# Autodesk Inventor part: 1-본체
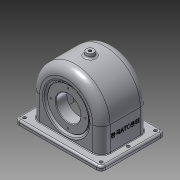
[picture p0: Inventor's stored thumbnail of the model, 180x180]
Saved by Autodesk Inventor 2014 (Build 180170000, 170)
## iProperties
Created: 2015-09
Part Number: 1-본체
Material: 알루미늄 6061
Document SubType Name: Modeling
Designer: Administrator
Density: 2.71 g/cm^3
Appearance: 알루미늄 - 평지
Mass: 735.164 g
Surface Area: 899.785 cm^2
Volume: 271.278 cm^3
Author: Administrator
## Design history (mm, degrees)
sketch "스케치2"
  geometry: L1 (57, 40)-(57, -7); L2 (-57, 40)-(-57, -7); L3 (57, -7)-(-57, -7); C1 r 51 at (0, 40); A1 r 57 centre (0, 40) between (57, 40) and (-57, 40); 2 further points
  constraints: 6 end point, 2 centre point, 2 point on circle, 2 tangent, 1 perpendicular, 1 vertical alignment
  dimensions: "d4" = 51 radius of C1; "d6" = 6 radial gap between concentric circles of C1 A1; "d27" = 40 distance of point (0, 0) C1.centre
extrude "돌출2" join sketch "스케치2" stored distance "d7" = 77; taper "d8" = 0 deg
fillet "모깎기1" dims "d11" = 14
feature "쉘4" dims "d30" = 6, "d31" = 5
sketch "스케치12"
  geometry: L1 (-43, -38.5)-(43, -38.5) reference; L2 (-57, -24.5)-(-57, 24.5) reference; L3 (43, 38.5)-(-43, 38.5) reference; L4 (57, -24.5)-(57, 24.5) reference; L5 (-70, -52)-(70, -52); L6 (70, -52)-(70, 52); L7 (70, 52)-(-70, 52); L8 (-70, 52)-(-70, -52); A1 r 14 centre (-43, -24.5) between (-57, -24.5) and (-43, -38.5) reference; A2 r 14 centre (-43, 24.5) between (-43, 38.5) and (-57, 24.5) reference; A3 r 14 centre (43, 24.5) between (57, 24.5) and (43, 38.5) reference; A4 r 14 centre (43, -24.5) between (43, -38.5) and (57, -24.5) reference; 3 further points
  constraints: 8 end point, 2 midpoint, 2 parallel, 1 horizontal, 1 horizontal alignment, 1 perpendicular, 1 vertical alignment
  dimensions: "d32" = 104 distance of L7.end L5.start; "d33" = 140 distance of L6.end L7.end
extrude "돌출5" join sketch "스케치12" distance "d34" = 7; taper "d35" = 0 deg
sketch "스케치8"
  geometry: L1 (-33.5, 40)-(-17.5, 40); L2 (-17.5, 40)-(-17.5, 68); L3 (-17.5, 68)-(-33.5, 81.426); L4 (-33.5, 81.426)-(-33.5, 40); L5 (-52, -7)-(52, -7) reference; L6 (-33.5, 40)-(-33.5, 83) reference; 1 further point
  constraints: 8 end point, 1 collinear, 1 horizontal, 1 parallel, 1 perpendicular
  dimensions: "d16" = 50 deg angle of L2 L3; "d17" = 16 distance of L1.start L1.end; "d18" = 28 distance of L1.end L2.end; "d36" = 47 distance from line of L1.start L5
revolve "회전1" sketch "스케치8" stored, may be unused: angle "d19" = 90 deg
sketch "스케치9"
  geometry: C1 r 31 at (0, -40); A1 r 43 centre (0, -40) between (-43, -40) and (43, -40) reference; 1 further point
  constraints: 1 centre point, 1 coincident
  dimensions: "d20" = 62 diameter of C1
extrude "돌출3" join sketch "스케치9" distance "d21" = 10; taper "d22" = 0 deg
node "작업 평면1"
sketch "스케치10"
  geometry: C1 r 6 at (70, 52); 1 further point
  constraints: 1 centre point, 1 coincident
  dimensions: "d24" = 12 diameter of C1
extrude "돌출4" join sketch "스케치10" stored distance "d25" = 10; taper "d26" = 10 deg
sketch "스케치16"
  geometry: L1 (-38.5, 40)-(-38.5, 77.195); L2 (-38.5, 77.195)-(-33.5, 73); L3 (-33.5, 73)-(-33.5, 40); L4 (-33.5, 40)-(-38.5, 40); L5 (-24.5, 40)-(24.5, 40) reference; L6 (-33.5, 81.426)-(-33.5, -1.426) reference; L7 (-38.5, 40)-(-38.5, 83) reference; L8 (-24.5, 40)-(-33.5, 40) reference; 1 further point
  constraints: 8 end point, 2 point on line, 1 collinear, 1 parallel, 1 perpendicular, 1 vertical
  dimensions: "d45" = 50 deg angle of L6 L2; "d46" = 33 distance from line of L8 L2.end
revolve "회전2" sketch "스케치16" stored, may be unused: angle "d47" = 90 deg
sketch "스케치17"
  geometry: C1 r 33 at (0, 0) reference; C2 r 33 at (0, 0); 1 further point
  constraints: 1 centre point, 1 coincident
  dimensions: "d48" = 66 diameter of C2
extrude "돌출8" join sketch "스케치17" distance "d49" = 2; taper "d50" = 0 deg
hole "구멍1" diameter "d53" = 40; stored, may be unused: countersink angle "d57" = 90 deg, drill point angle "d59" = 118 deg; dims "d51" = 10, "d52" = 10, "d54" = 6, "d55" = 4, "d56" = 2, "d58" = 8
sketch "스케치18"
  geometry: L1 (0, 0)-(0, 28); C1 r 20 at (0, 0) reference; 1 further point
  constraints: 2 end point, 1 coincident, 1 vertical
  dimensions: "d60" = 28 distance of L1.start L1.end
hole "구멍2" sketch "스케치18" at (0, 28) diameter "d61" = 2.459; stored, may be unused: countersink angle "d65" = 90 deg, drill point angle "d67" = 118 deg; dims "d62" = 7, "d63" = 4, "d64" = 2, "d66" = 9
sketch "스케치19"
  geometry: L1 (0, 0)-(0, -24); C1 r 20 at (0, 0) reference; 1 further point
  constraints: 2 end point, 1 coincident, 1 vertical
  dimensions: "d71" = 24 distance of L1.start L1.end
hole "구멍3" sketch "스케치19" at (0, -24) diameter "d72" = 2.459; stored, may be unused: countersink angle "d76" = 90 deg, drill point angle "d78" = 118 deg; dims "d73" = 6, "d74" = 4, "d75" = 2, "d77" = 8
sketch "스케치20"
  geometry: 1 further point
hole "구멍4" sketch "스케치20" at (0, 0) diameter "d82" = 4.459; stored, may be unused: countersink angle "d86" = 90 deg, drill point angle "d88" = 0 deg; dims "d83" = 7, "d84" = 4, "d85" = 2, "d87" = 9
sketch "스케치21"
  geometry: L1 (15.664, 0.636)-(15.664, 48.364); L2 (15.664, 48.364)-(18.336, 48.364); L3 (18.336, 48.364)-(18.336, 0.636); L4 (18.336, 0.636)-(15.664, 0.636); L5 (47, 76.5)-(47, -27.5) reference; L6 (0, -14)-(40, -14) reference; 4 further points
  constraints: 3 midpoint, 1 horizontal alignment, 2 other
  dimensions: "d89" = 38.5 distance from line of L6 point (18.336, 24.5) (derived); "d90" = 30 distance from line of L5 point (17, 48.364)
feature "엠보싱1" sketch "스케치21" dims "d91" = 0.5, "d92" = 0
fillet "모깎기2" dims "d93" = 3
fillet "모깎기3" dims "d94" = 0.5
fillet "모깎기4" dims "d95" = 1
fillet "모깎기5" dims "d96" = 7
fillet "모깎기6" dims "d97" = 3
chamfer "모따기1" distance "d98" = 1; stored, may be unused: second distance "d99" = 2, angle "d100" = 45 deg
fillet "모깎기7" dims "d101" = 3
sketch "스케치22"
  geometry: L1 (-62, 44)-(62, 44); L2 (62, 44)-(62, -44); L3 (62, -44)-(-62, -44); L4 (-62, -44)-(-62, 44); 4 further points
  constraints: 8 end point, 3 midpoint, 2 parallel, 1 horizontal, 1 horizontal alignment, 1 perpendicular, 1 vertical alignment
  dimensions: "d102" = 124 distance of L2.end L3.end; "d103" = 44 distance of point (62, 0) L1.end; "d104" = 44 distance of L2.end point (62, 0) (derived)
hole "구멍5" sketch "스케치22" at (62, 0), (-62, 44), (-62, 0), (-62, -44), (62, -44), (62, 44) diameter "d105" = 5; stored, may be unused: countersink angle "d109" = 90 deg, drill point angle "d111" = 0 deg; dims "d106" = 6, "d107" = 4, "d108" = 2, "d110" = 8
node "솔리드1"
pattern_circular "원형 패턴1" dims angle "d69" = 360 deg
pattern_circular "원형 패턴2" dims angle "d80" = 360 deg
